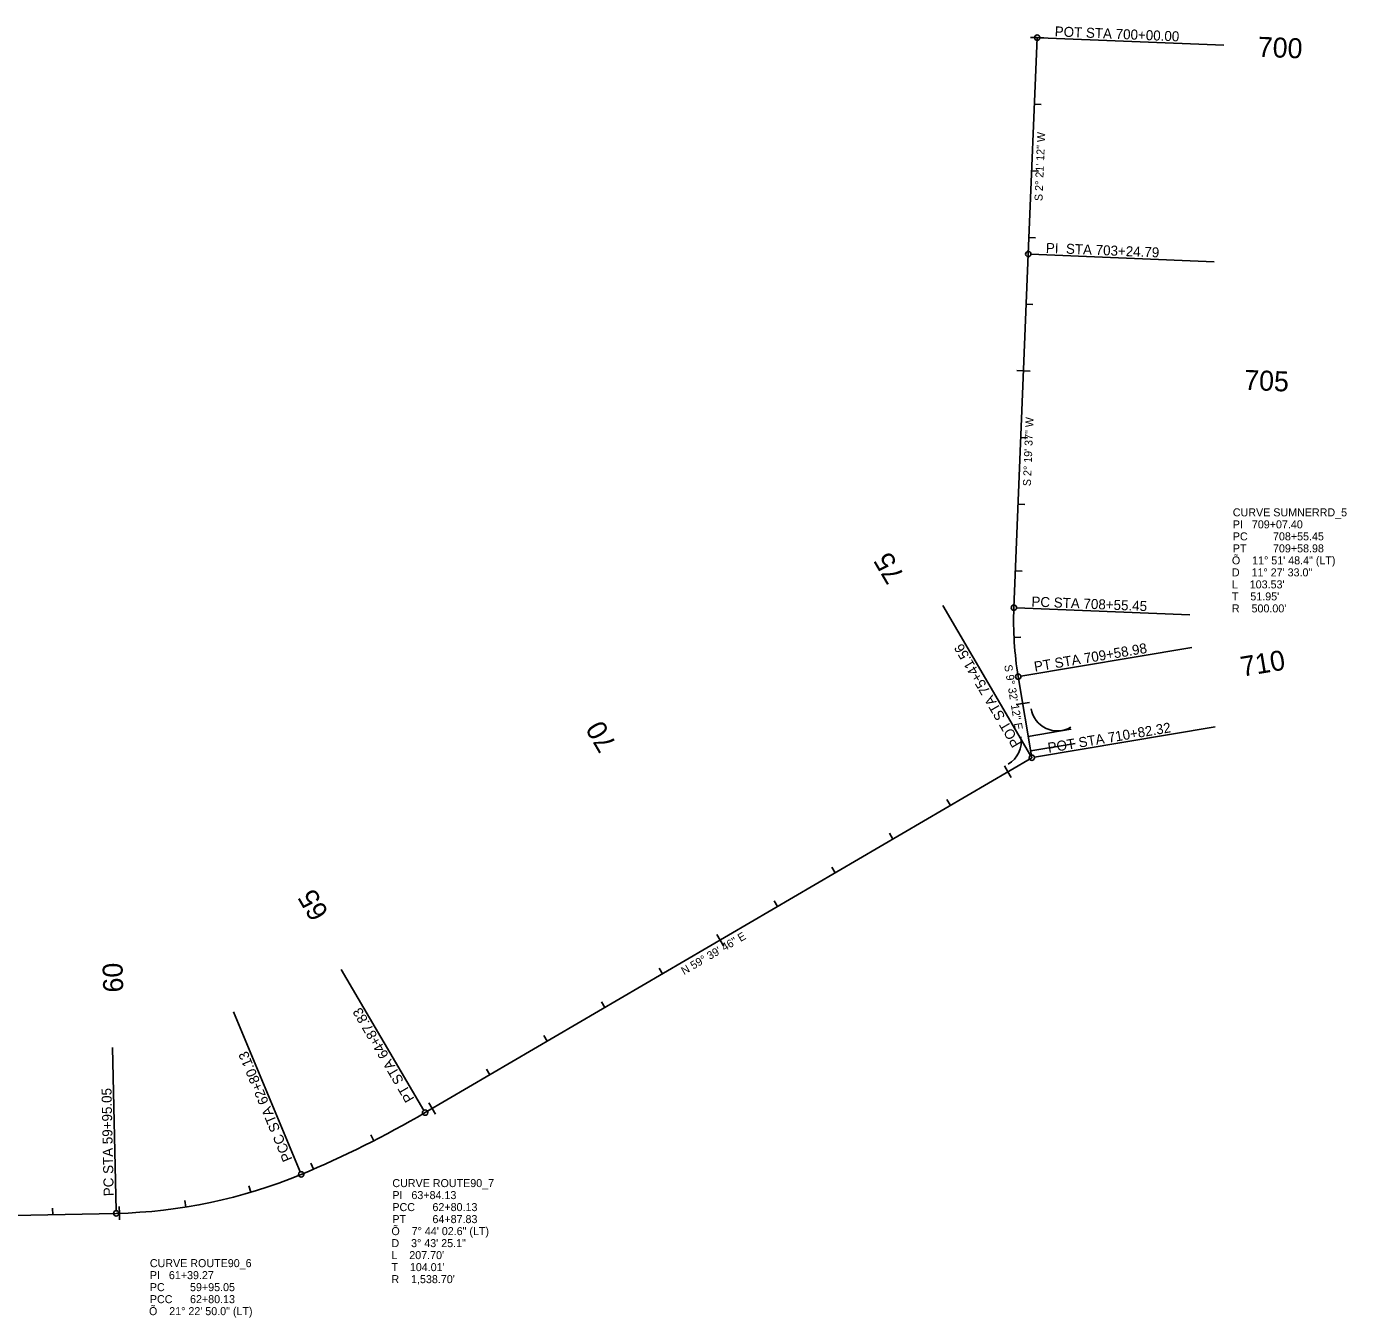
# Model space of a CAD drawing. Extents: x 2819977 to 2827606, y 116785 to 150320.
# Drawn here: x 2821928 to 2823907, y 131992 to 133928 of the extents above; entities that cross this region are included whole.
import ezdxf

# ---------------------------------------------------------------- set-up
doc = ezdxf.new("R2010")
doc.units = 0
for name, color, linetype in [('Default', 7, 'Continuous'), ('Modeling-Contours-Major-Existing', 7, 'Continuous'), ('Modeling-Contours-Minor-Existing', 7, 'Continuous'), ('Modeling-Flow Arrows-Existing', 7, 'Continuous'), ('Modeling-Spot-Existing', 7, 'Continuous'), ('Modeling-Triangle Verticies-Existing', 7, 'Continuous')]:
    doc.layers.add(name, color=color, linetype=linetype)

msp = doc.modelspace()

# ---------------------------------------------------------------- linework, layer by layer
at = {"layer": 'Default'}
msp.add_line((2821496.2, 132136.6), (2822062.3, 132148.7), dxfattribs=at)
for centre, radius, start, end in [((2823907.5, 133036.4), 500, 177.6731, 189.5366), ((2821748.2, 133627.7), 1538.7, 292.6032, 300.3373), ((2822046, 132912.4), 763.9, 271.2227, 292.6032)]:
    msp.add_arc(centre, radius, start, end, dxfattribs=at)
at = {"layer": 'Modeling-Contours-Major-Existing'}
msp.add_line((2823433.1, 132842), (2823499.9, 132853.3), dxfattribs=at)
msp.add_lwpolyline([(2823429.5, 132863.8), (2823493.3, 132874.5), (2823493.3, 132874.5)], dxfattribs=at)
for centre, start, end in [((2823473.1, 132912), 189.5366, 300.1522), ((2823379, 132856.6), 300.4712, 9.5366)]:
    msp.add_arc(centre, 40, start, end, dxfattribs=at)
at = {"layer": 'Modeling-Flow Arrows-Existing'}
for p, q in [((2823442.8, 133911.4), (2823429.5, 133586.9)), ((2823442.8, 133911.4), (2823432.8, 133911.8)), ((2823442.8, 133911.4), (2823452.8, 133911)), ((2823438.7, 133811.5), (2823448.7, 133811.1)), ((2823434.6, 133711.6), (2823444.6, 133711.2)), ((2823430.5, 133611.7), (2823440.5, 133611.3)), ((2823429.5, 133586.9), (2823407.9, 133056.7)), ((2823426.4, 133511.8), (2823436.4, 133511.4)), ((2823422.3, 133411.8), (2823412.3, 133412.2)), ((2823422.3, 133411.8), (2823432.3, 133411.4)), ((2823418.3, 133311.9), (2823428.3, 133311.5)), ((2823414.2, 133212), (2823424.2, 133211.6)), ((2823410.2, 133112.1), (2823420.1, 133111.7)), ((2823408.1, 133012.2), (2823418.1, 133012.6)), ((2823414.4, 132953.5), (2823434.8, 132831.9)), ((2823421.2, 132913.1), (2823411.3, 132911.4)), ((2823421.2, 132913.1), (2823431.1, 132914.7)), ((2822525.4, 132299.7), (2823434.8, 132831.9)), ((2823399, 132810.9), (2823393.9, 132819.6)), ((2823399, 132810.9), (2823404, 132802.3)), ((2823312.7, 132760.4), (2823307.6, 132769)), ((2823226.4, 132709.9), (2823221.3, 132718.5)), ((2823140, 132659.4), (2823135, 132668)), ((2823053.7, 132608.9), (2823048.7, 132617.5)), ((2822967.4, 132558.4), (2822962.4, 132567)), ((2822967.4, 132558.4), (2822972.5, 132549.7)), ((2822881.1, 132507.9), (2822876.1, 132516.5)), ((2822794.8, 132457.4), (2822789.8, 132466)), ((2822708.5, 132406.9), (2822703.5, 132415.5)), ((2822622.2, 132356.3), (2822617.2, 132365)), ((2822535.9, 132305.8), (2822530.8, 132314.5)), ((2822535.9, 132305.8), (2822541, 132297.2)), ((2822448.4, 132257.5), (2822443.8, 132266.4)), ((2822357.9, 132214.9), (2822353.9, 132224.1)), ((2822264.2, 132180.3), (2822261.3, 132189.9)), ((2821967.3, 132146.6), (2821967, 132156.6)), ((2822067.2, 132148.8), (2822067, 132158.8)), ((2822166.7, 132158.1), (2822165.2, 132168)), ((2821496.2, 132136.6), (2822062.3, 132148.7)), ((2822067.2, 132148.8), (2822067.5, 132138.8))]:
    msp.add_line(p, q, dxfattribs=at)
for centre, radius, start, end in [((2823907.5, 133036.4), 500, 177.6731, 189.5366), ((2821748.2, 133627.7), 1538.7, 292.6032, 300.3373), ((2822046, 132912.4), 763.9, 271.2227, 292.6032)]:
    msp.add_arc(centre, radius, start, end, dxfattribs=at)
at = {"layer": 'Modeling-Spot-Existing'}
for p, q in [((2823446.8, 133911.3), (2823722.5, 133899.9)), ((2823433.4, 133586.7), (2823708, 133575.5)), ((2823432.8, 132835.4), (2823301.3, 133060.2)), ((2823411.9, 133056.5), (2823671.5, 133046)), ((2823418.3, 132954.2), (2823674.5, 132997.2)), ((2823438.8, 132832.6), (2823709.7, 132878.1)), ((2822523.4, 132303.1), (2822399.8, 132514.4)), ((2822338.1, 132210.9), (2822238.2, 132450.7)), ((2822062.2, 132152.7), (2822057, 132397.4))]:
    msp.add_line(p, q, dxfattribs=at)
for centre in [(2823442.8, 133911.4), (2823429.5, 133586.9), (2823407.9, 133056.7), (2823414.4, 132953.5), (2823434.8, 132831.9), (2823434.8, 132831.9), (2822525.4, 132299.7), (2822339.6, 132207.2), (2822062.3, 132148.7)]:
    msp.add_circle(centre, 4, dxfattribs=at)

# ---------------------------------------------------------------- texts
at = {"layer": 'Modeling-Contours-Minor-Existing'}
for s, rotation, p in [('S 2%%d 21\' 12" W', 87.6466, (2823450.7, 133666.2)), ('S 2%%d 19\' 37" W', 87.6731, (2823433.3, 133238.8)), ('S 9%%d 32\' 12" E', 279.5366, (2823393.3, 132970.4)), ('N 59%%d 39\' 46" E', 30.3373, (2822913.5, 132505.9))]:
    msp.add_text(s, height=12, rotation=rotation, dxfattribs=at).set_placement(p)
at = {"layer": 'Modeling-Flow Arrows-Existing'}
for s, rotation, p in [(' 700', 357.6466, (2823761.9, 133883.3)), (' 705', 357.6731, (2823741.5, 133383.9)), (' 75', 120.3373, (2823250.3, 133094.7)), (' 710', 9.5366, (2823739.3, 132951.3)), (' 70', 120.3373, (2822818.8, 132842.1)), (' 65', 120.3373, (2822387.2, 132589.6)), (' 60', 91.5938, (2822073.3, 132469.1))]:
    msp.add_text(s, height=30, rotation=rotation, dxfattribs=at).set_placement(p)
at = {"layer": 'Modeling-Spot-Existing'}
for s, rotation, p in [('POT STA 700+00.00', 357.6466, (2823468.9, 133913.4)), ('PI  STA 703+24.79', 357.6466, (2823455.6, 133588.8)), ('PC STA 708+55.45', 357.6731, (2823434, 133058.6)), ('POT STA 75+41.56', 120.3373, (2823419.1, 132852.8)), ('PT STA 709+58.98', 9.5366, (2823439.5, 132960.8)), ('POT STA 710+82.32', 9.5366, (2823460, 132839.2)), ('PT STA 64+87.83', 120.3373, (2822509.7, 132320.6)), ('PCC STA 62+80.13', 112.6032, (2822326.8, 132230)), ('PC STA 59+95.05', 91.2227, (2822058.7, 132174.6))]:
    msp.add_text(s, height=15, rotation=rotation, dxfattribs=at).set_placement(p)
at = {"layer": 'Modeling-Triangle Verticies-Existing'}
for s, p in [('CURVE SUMNERRD_5', (2823736.1, 133193.7)), ('PI   709+07.40', (2823736.1, 133175.7)), ('PC', (2823736.1, 133157.7)), ('708+55.45', (2823796.3, 133157.7)), ('PT', (2823736.1, 133139.7)), ('709+58.98', (2823796.3, 133139.7)), ('Õ    11%%d 51\' 48.4" (LT)', (2823734.7, 133121.7)), ('D    11%%d 27\' 33.0"', (2823734.7, 133103.7)), ("T    51.95'", (2823734.7, 133067.7)), ("L    103.53'", (2823734.7, 133085.7)), ("R    500.00'", (2823734.7, 133049.7)), ('CURVE ROUTE90_7', (2822476.3, 132188.1)), ('PI   63+84.13', (2822476.3, 132170.1)), ('PCC', (2822476.3, 132152.1)), ('62+80.13', (2822536.4, 132152.1)), ('Õ    7%%d 44\' 02.6" (LT)', (2822474.9, 132116.1)), ('PT', (2822476.3, 132134.1)), ('64+87.83', (2822536.4, 132134.1)), ('D    3%%d 43\' 25.1"', (2822474.9, 132098.1)), ("L    207.70'", (2822474.9, 132080.1)), ('CURVE ROUTE90_6', (2822112.8, 132068.1)), ("T    104.01'", (2822474.9, 132062.1)), ('PI   61+39.27', (2822112.8, 132050.1)), ("R    1,538.70'", (2822474.9, 132044.1)), ('PC', (2822112.8, 132032.1)), ('59+95.05', (2822173, 132032.1)), ('Õ    21%%d 22\' 50.0" (LT)', (2822111.5, 131996.1)), ('PCC', (2822112.8, 132014.1)), ('62+80.13', (2822173, 132014.1))]:
    msp.add_text(s, height=12, dxfattribs=at).set_placement(p)

doc.saveas('drawing.dxf')
